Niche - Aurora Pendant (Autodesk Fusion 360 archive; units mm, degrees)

design "Aurora" references "Luxe Single Pendant Cordset - 4ft Standard", "Aurora", "T9-5In"
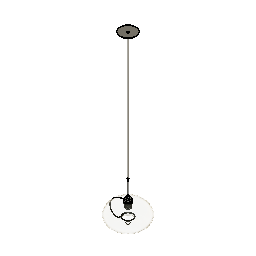
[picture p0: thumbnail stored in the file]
external_derived "ExternalDerived1"
external_derived "ExternalDerived2" bodies "Socket Body", "Shade Ring", "Shade Ring +Collar", "Socket", "Body1", "Metal Strain Relief", "Fabric Cord (1)", "Stem (Threaded)"
move "Move1"
external_derived "ExternalDerived3" bodies "Body1 (1)"
align "Align1"
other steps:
derived_base_feature "Derived Base Feature1" bodies "Body6"
derived_base_feature "Derived Base Feature2" bodies "Socket Body", "Shade Ring", "Shade Ring +Collar", "Socket", "Body1", "Metal Strain Relief", "Fabric Cord (1)", "Stem (Threaded)"
derived_base_feature "Derived Base Feature3" bodies "Body1 (1)"
named bodies: "Body6", "Socket Body", "Shade Ring", "Shade Ring +Collar", "Socket", "Body1", "Metal Strain Relief", "Fabric Cord (1)", "Stem (Threaded)", "Cap (Threaded)", "Body1 (1)"

design "Luxe Single Pendant Cordset - 4ft Standard" references "Luxe Canopy - Single Pendant Cordset"
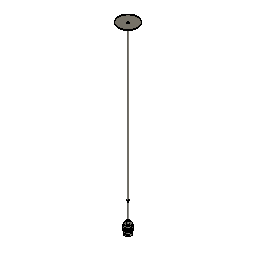
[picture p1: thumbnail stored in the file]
external_derived "ExternalDerived2" bodies "Cap (Threaded)"
move "Move1"
move "Move2"
offset_faces "OffsetFaces1" distance 1051.56
move "Move3"
move "Move4"
move "Move5"
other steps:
derived_base_feature "Derived Base Feature9" bodies "Socket Body", "Shade Ring", "Shade Ring +Collar", "Socket"
derived_base_feature "Derived Base Feature10" bodies "Body1"
derived_base_feature "Derived Base Feature12" bodies "Metal Strain Relief"
derived_base_feature "Derived Base Feature13" bodies "Fabric Cord (1)"
derived_base_feature "Derived Base Feature14" bodies "Stem (Threaded)"
derived_base_feature "Derived Base Feature15" bodies "Cap 9Threaded)", "Cap (Threaded)"
named bodies: "Socket Body", "Shade Ring", "Shade Ring +Collar", "Socket", "Metal Strain Relief", "Fabric Cord (1)", "Stem (Threaded)", "Cap 9Threaded)", "Body1", "Cap (Threaded)", "5M Set Screw"

design "Niche_Aurora_Single_Pendant"
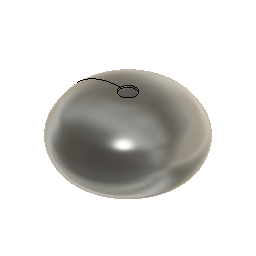
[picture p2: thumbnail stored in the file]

design "Aurora" references "Niche_Aurora_Single_Pendant"
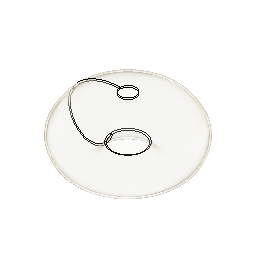
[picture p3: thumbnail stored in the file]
external_derived "ExternalDerived"
move "Move1" PositionX -19.05 PositionY 0 PositionZ 0
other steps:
derived_base_feature "Derived Base Feature" bodies "Body6"
named bodies: "Body6"

design "T9-5In"
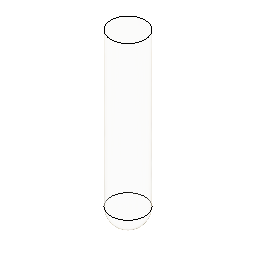
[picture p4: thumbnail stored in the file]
sketch "Sketch1" plane through (0, 0, 0) normal (0, 1, 0) x axis (1, 0, 0)
  line L1 (0, 0) -> (0, -127)
  line L2 (12.7, -127) -> (-12.7, -127)
  line L3 (12.7, -12.7) -> (12.7, -127)
  line L4 (-12.7, -127) -> (-12.7, -12.7)
  arc A1 centre (0, -12.7) radius 12.7 clockwise from (-12.7, -12.7) to (12.7, -12.7)
  point P1 (0, 0)
  point P3 (0, 0)
  coincident P1 P3
  vertical L1
  horizontal L2
  vertical L3
  vertical L4
revolve "Revolve1" sketch "Sketch1" AlongAngle 360

design "Luxe Canopy - Single Pendant Cordset" references "Luxe Cordset", "Canopy Mounting Bar", "M5 Set Screw", "Canopy Mounting Bar Screw", "Plastic Strain Relief"
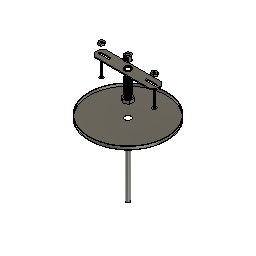
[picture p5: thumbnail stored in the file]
sketch "Sketch1" plane through (0, 0, 0) normal (0, 0, 1) x axis (1, 0, 0)
  circle C1 centre (0, 0) radius 63.5
  point P1 (0, 0)
  point P2 (0, 0)
  coincident P1 P2
  dimension "d1" diameter C1 = 127
extrude "Extrude1" new body sketch "Sketch1" along normal blind 5.08
shell "Shell1" innerThickness 0.762
hole "Hole1" HoleDepth 35.56 HoleDiameter 10.16 TipAngle 118
component_from_bodies "Body->Comp1"
component_insert "Component Insert1"
component_insert "Component Insert2"
component_insert "Component Insert3"
sketch "Sketch2" plane through (0, 0, 0) normal (0, 0, 1) x axis (1, 0, 0)
  circle C1 centre (0, 0) radius 3.175
  point P1 (0, 0)
  point P2 (0, 0)
  coincident P1 P2
  dimension "d8" diameter C1 = 6.35
extrude "Extrude2" new body sketch "Sketch2" along normal blind 127 and against normal blind 127 bodies "Fabric Cord"
component_insert "Component Insert4"
component_insert "Component Insert5"
position "Position1"
sketch "Sketch3" plane through (0, 0, 0.762) normal (0, 0, 1) x axis (-1, 0, 0)
  circle C1 centre (-0.0475, 0.2257) radius 5.08
  circle C2 centre (0, 0) radius 62.738
  circle C3 centre (0, 0) radius 4.826
  concentric C2 C3
  dimension "d13" diameter C3 = 9.652
extrude "Extrude3" new body sketch "Sketch3" profile of C3 along normal blind 25.4 bodies "Threaded Nipple"
shell "Shell2" innerThickness 1.27
thread "Thread1"
sketch "Sketch5" plane through (0, 0, 127) normal (0, 0, 1) x axis (-1, 0, 0)
  line L1 (-6.8191, 3.937) -> (0, 7.874)
  line L2 (-6.8191, -3.937) -> (-6.8191, 3.937)
  line L3 (0, -7.874) -> (-6.8191, -3.937)
  line L4 (6.8191, -3.937) -> (0, -7.874)
  line L5 (6.8191, 3.937) -> (6.8191, -3.937)
  line L6 (0, 7.874) -> (6.8191, 3.937)
  circle C1 centre (0, 0) radius 3.175
  point P2 (0, 0)
  point P9 (0, 0)
  point P3 (0, 7.874)
  coincident P2 P9
  dimension "d20" distance P3 P9 = 7.874
extrude "Extrude4" new body sketch "Sketch5" along normal blind 5.08 bodies "Hex Nut"
move "Move1"
thread "Thread2"
move "Move2" TranslateX 0 TranslateY 0 TranslateZ -55.88
move "Move3" TranslateX 0 TranslateY 0 TranslateZ 60.96
position "Position2"
sketch "Sketch6" plane through (0, 0, 0) normal (0, 0, 1) x axis (1, 0, 0)
  circle C1 centre (0, 0) radius 9.525
  point P1 (0, 0)
  point P2 (0, 0)
  coincident P1 P2
  dimension "d29" diameter C1 = 19.05
extrude "Extrude5" new body sketch "Sketch6" along normal blind 16.129 bodies "Metal Strain Relief"
move "Move4" TranslateX 0 TranslateY 0 TranslateZ -86.36
hole "Hole2" HoleDepth 10.16 HoleDiameter 5.08 TipAngle 118
hole "Hole3" HoleDepth 4.064 HoleDiameter 7.62 TipAngle 180
hole "Hole4" HoleDepth 12.192 HoleDiameter 9.144 TipAngle 180
thread "Thread3" ThreadOffset 0 ThreadLength 6.096
move "Move1" TranslateX 0 TranslateY 0 TranslateZ 68.58
move "Move5" TranslateX 0 TranslateY 0 TranslateZ 138.43
component_insert "Component Insert6"
external_derived "ExternalDerived1" bodies "5M Set Screw"
move "Move6" TranslateX 0 TranslateY 0 TranslateZ -185.42
copy_paste_bodies "CopyPasteBodies1"
move "Move7" TranslateX 0 TranslateY 0 TranslateZ -12.7
offset_faces "OffsetFaces1" distance -152.4
move "Move8"
component_from_bodies "Body->Comp2"
component_from_bodies "Body->Comp3"
component_from_bodies "Body->Comp4"
component_from_bodies "Body->Comp5"
hole "Hole1" HoleDepth 25.4 HoleDiameter 6.35 TipAngle 180
sketch "Sketch7" plane through (0, 0, 0) normal (0, 0, 1) x axis (1, 0, 0)
  line L1 (49.784, 3.9595) -> (52.07, 0)
  line L2 (45.212, 3.9595) -> (49.784, 3.9595)
  line L3 (42.926, 0) -> (45.212, 3.9595)
  line L4 (45.212, -3.9595) -> (42.926, 0)
  line L5 (49.784, -3.9595) -> (45.212, -3.9595)
  line L6 (52.07, 0) -> (49.784, -3.9595)
  point P2 (52.07, 0)
  point P8 (47.498, 0)
  dimension "d63" distance P2 P8 = 4.572
extrude "Extrude6" new body sketch "Sketch7" along normal blind 3.175 bodies "Mounting Hex Nut"
hole "Hole5" HoleDepth 25.4 HoleDiameter 3.81 TipAngle 180
thread "Thread4"
move "Move9"
component_from_bodies "Body->Comp6"
copy_paste "CopyPaste1"
move "Move10"
derived_base_feature "Derived Base Feature3" bodies "Stem (Threaded)", "Cap 9Threaded)"
move "Move11"
component_from_bodies "Body->Comp7"
component_from_bodies "Body->Comp8"
component_from_bodies "Body->Comp9"
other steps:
base_feature "Base Feature1"
base_feature "Base Feature1" bodies "Stem (Threaded)"
base_feature "Base Feature1" bodies "Cap 9Threaded)"
base_feature "Base Feature1" bodies "Fabric Cord"
base_feature "Base Feature1" bodies "Metal Strain Relief"
base_feature "Base Feature1" bodies "Mounting Hex Nut"
base_feature "Base Feature1" bodies "Hex Nut"
base_feature "Base Feature1" bodies "Fabric Cord (1)"
base_feature "Base Feature1" bodies "Threaded Nipple"
derived_base_feature "Derived Base Feature1" bodies "Socket Body", "Shade Ring", "Shade Ring +Collar", "Socket", "Rigid Stem"
derived_base_feature "Derived Base Feature2" bodies "5M Set Screw"
base_feature "Base Feature1" bodies "Fabric Cord", "Fabric Cord (1)"
create_component "CreateComponent1"
remove_body "RemoveBody1"
create_component "CreateComponent2"
remove_body "RemoveBody2"
create_component "CreateComponent3"
remove_body "RemoveBody3"
create_component "CreateComponent4"
remove_body "RemoveBody4"
create_component "CreateComponent5"
remove_body "RemoveBody5"
create_component "CreateComponent6"
remove_body "RemoveBody6"
create_component "CreateComponent7"
remove_body "RemoveBody7"
create_component "CreateComponent8"
remove_body "RemoveBody8"
create_component "CreateComponent9"
remove_body "RemoveBody9"
named bodies: "Fabric Cord", "Threaded Nipple", "Hex Nut", "Metal Strain Relief", "Socket Body", "Shade Ring", "Shade Ring +Collar", "Socket", "Rigid Stem", "5M Set Screw", "Fabric Cord (1)", "Mounting Hex Nut", "Stem (Threaded)", "Cap 9Threaded)"

design "M5 Set Screw"
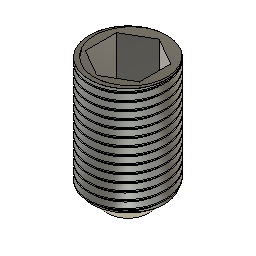
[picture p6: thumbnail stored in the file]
sketch "Sketch1" plane through (0, 0, 0) normal (0, 0, 1) x axis (1, 0, 0)
  circle C1 centre (0, 0) radius 2.5
  point P1 (0, 0)
  point P2 (0, 0)
  coincident P1 P2
  dimension "d1" diameter C1 = 5
extrude "Extrude1" new body sketch "Sketch1" along normal blind 8
sketch "Sketch2" plane through (0, 0, 8) normal (0, 0, 1) x axis (-1, 0, 0)
  line L1 (-1.7321, 1) -> (0, 2)
  line L2 (-1.7321, -1) -> (-1.7321, 1)
  line L3 (0, -2) -> (-1.7321, -1)
  line L4 (1.7321, -1) -> (0, -2)
  line L5 (1.7321, 1) -> (1.7321, -1)
  line L6 (0, 2) -> (1.7321, 1)
  circle C1 centre (0, 0) radius 2.5
  point P2 (0, 0)
  point P9 (0, 0)
  coincident P2 P9
extrude "Extrude2" cut sketch "Sketch2" profile of L1 L2 L3 L4 L5 L6 against normal blind 3
thread "Thread1" ThreadOffset 0.99 ThreadLength 7
chamfer "Chamfer1" distance 1.15

design "Luxe Cordset" references "M5 Set Screw"
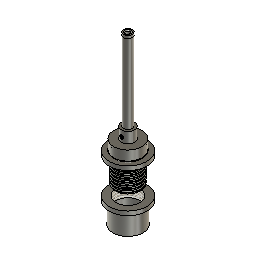
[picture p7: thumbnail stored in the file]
sketch "Sketch1" plane through (0, 0, 0) normal (0, 0, 1) x axis (1, 0, 0)
  circle C1 centre (0, 0) radius 20.6
  point P1 (0, 0)
  point P2 (0, 0)
  coincident P1 P2
  dimension "d11" diameter C1 = 41.2
extrude "Extrude1" new body sketch "Sketch1" along normal blind 14 bodies "Socket Body"
sketch "Sketch2" plane through (0, 0, 14) normal (0, 0, 1) x axis (-1, 0, 0)
  circle C1 centre (0, 0) radius 20.6
  circle C2 centre (0, 0) radius 9.6
  concentric C1 C2
  dimension "d3" diameter C2 = 19.2
extrude "Extrude2" add sketch "Sketch2" profile of C2 along normal blind 15.75
sketch "Sketch3" plane through (0, 0, 29.75) normal (0, 0, 1) x axis (-1, 0, 0)
  circle C1 centre (0, 0) radius 9.6
  circle C2 centre (0, 0) radius 5.75
  concentric C1 C2
  dimension "d6" diameter C2 = 11.5
extrude "Extrude3" new body sketch "Sketch3" profile of C2 along normal blind 114 bodies "Rigid Stem"
move "Move1"
sketch "Sketch4" plane through (0, 0, 203.75) normal (0, 0, 1) x axis (-1, 0, 0)
  circle C1 centre (0, 0) radius 5.75
  circle C2 centre (0, 0) radius 27.5
  dimension "d10" diameter C2 = 55
extrude "Extrude4" new body sketch "Sketch4" profile of C2 along normal blind 6 bodies "Shade Ring"
hole "Hole1" HoleDepth 25 HoleDiameter 42.75 TipAngle 118
sketch "Sketch5" plane through (0, 0, 0) normal (0, 0, 1) x axis (1, 0, 0)
  circle C1 centre (0, 0) radius 22
  point P1 (0, 0)
  point P2 (0, 0)
  coincident P1 P2
  dimension "d18" diameter C1 = 44
move "Move2"
copy_paste_bodies "CopyPasteBodies1"
move "Move3"
sketch "Sketch6" plane through (0, 0, 60) normal (0, 0, -1) x axis (1, 0, 0)
  circle C1 centre (0, 0) radius 20.6
  circle C2 centre (0, 0) radius 21.375
  circle C3 centre (0, 0) radius 20
  concentric C1 C2
  concentric C1 C3
  dimension "d21" diameter C2 = 42.75
  dimension "d24" diameter C3 = 40
cylinder_primitive "CylinderPrimitive1" Height 8 Diameter 42.75
thread "Thread1"
thread "Thread3"
hole "Hole2" HoleDepth 18 HoleDiameter 39 TipAngle 180
move "Move4"
move "Move5"
move "Move6"
hole "Hole3" HoleDepth 114 HoleDiameter 7.6 TipAngle 180
derived_base_feature "Derived Base Feature" bodies "Socket"
move "Move7"
scale "Scale1" ScaleX 1.2 ScaleY 1.2
move "Move8"
sketch "Sketch8" plane through (0, 0, -23.9827) normal (0, 0, -1) x axis (1, 0, 0)
  circle C1 centre (0, -0.036) radius 27.5
  circle C2 centre (0, -0.036) radius 22
  circle C3 centre (0, -0.036) radius 19.5
  dimension "d36" diameter C2 = 44
  dimension "d42" = -2.5
extrude "Extrude7" add sketch "Sketch8" profile of C2 C3 along normal blind 30
offset_faces "OffsetFaces1" distance 2.75
offset_faces "OffsetFaces2" distance -9
thread "Thread2"
move "Move9"
move "Move10"
move "Move11"
scale "Scale2" ScaleZ 1.2
move "Move12"
move "Move13"
move "Move14"
move "Move15"
move "Move16"
split_face "SplitFace1"
move "Move17"
move "Move18"
move "Move19"
move "Move20"
move "Move21"
move "Move22"
move "Move23"
move "Move24"
move "Move25"
move "Move26"
move "Move27"
thread "Thread4"
move "Move28"
move "Move29"
move "Move30"
hole "Hole4" HoleDepth 21 HoleDiameter 39.35 TipAngle 180
hole "Hole5" HoleDepth 9 HoleDiameter 5 TipAngle 180
move "Move31"
move "Move32"
hole "Hole6" HoleDepth 20 HoleDiameter 10 TipAngle 180
move_face "MoveFace3"
move "Move33"
move "Move34"
move "Move35"
move "Move36"
move "Move37"
thread "Thread5" ThreadOffset 0 ThreadLength 6
thread "Thread6" ThreadOffset 0 ThreadLength 6
move "Move38"
move "Move39"
move "Move40"
move "Move41"
component_insert "Component Insert"
thread "Thread7" ThreadOffset 0.5 ThreadLength 5.337
chamfer "Chamfer1" distance 0.5 distance 0.35
sketch "Sketch12" plane through (0, 0, 0) normal (0, 0, 1) x axis (1, 0, 0)
  circle C1 centre (0, 0) radius 6.35
  dimension "d60" diameter C1 = 12.7
extrude "Extrude8" new body sketch "Sketch12" along normal blind 115 bodies "Stem (Threaded)"
hole "Hole7" HoleDepth 115 HoleDiameter 9.65 TipAngle 118
thread "Thread8" ThreadOffset 0 ThreadLength 12.5
thread "Thread9" ThreadOffset 0 ThreadLength 12.5
sketch "Sketch13" plane through (0, 0, 0) normal (0, 0, 1) x axis (1, 0, 0)
  circle C1 centre (0, 0) radius 6.35
  point P1 (0, 0)
  point P2 (0, 0)
  coincident P1 P2
  dimension "d70" diameter C1 = 12.7
extrude "Extrude9" new body sketch "Sketch13" along normal blind 4 bodies "Cap 9Threaded)"
sketch "Sketch14" plane through (0, 0, 4) normal (0, 0, 1) x axis (-1, 0, 0)
  circle C1 centre (0, 0) radius 6.35
  circle C2 centre (0, 0) radius 4.5
  concentric C1 C2
  dimension "d73" diameter C2 = 9
extrude "Extrude10" add sketch "Sketch14" profile of C2 against normal blind 14
thread "Thread10"
hole "Hole8" HoleDepth 115 HoleDiameter 6.5 TipAngle 118 CSDiameter 9 CSAngle 90
move "Move42"
move "Move43"
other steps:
base_feature "Base Feature" bodies "Shade Ring +Collar"
named bodies: "Socket Body", "Shade Ring", "Shade Ring +Collar", "Socket", "Rigid Stem", "Stem (Threaded)", "Cap 9Threaded)"

design "Plastic Strain Relief"
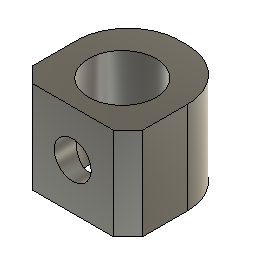
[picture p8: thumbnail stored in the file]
base_feature "Base Feature" bodies "strainrelief"
named bodies: "strainrelief"

design "Canopy Mounting Bar Screw"
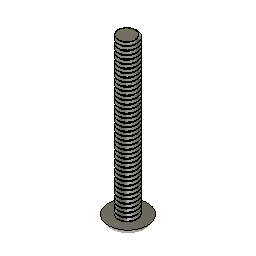
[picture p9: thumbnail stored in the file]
base_feature "Base Feature" bodies "screw1"
named bodies: "screw1"

design "Canopy Mounting Bar"
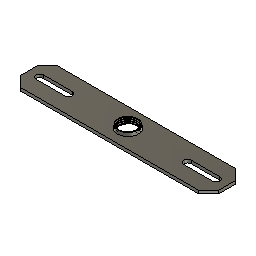
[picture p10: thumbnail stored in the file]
base_feature "Base Feature" bodies "mountingbar"
named bodies: "mountingbar"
